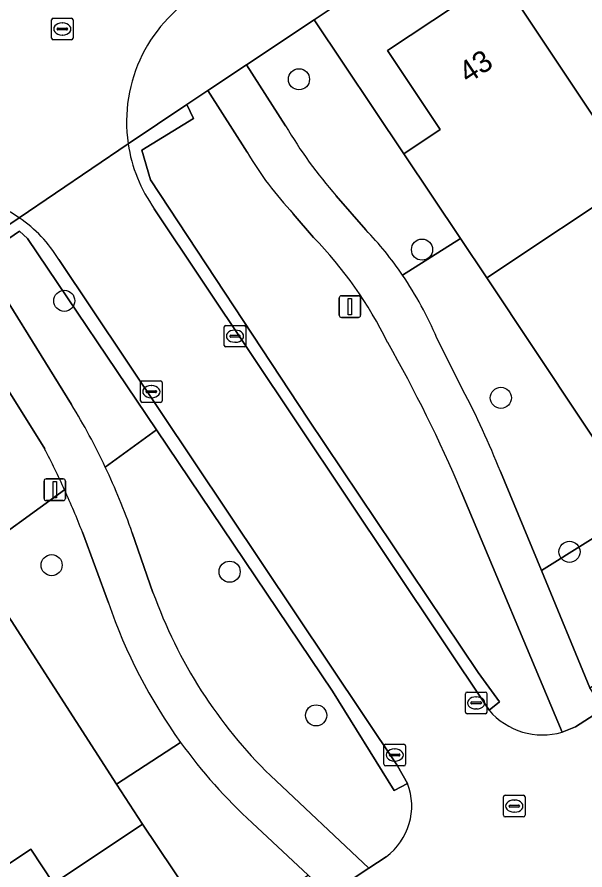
# Model space of a CAD drawing. Extents: x 158352 to 159489, y 383828 to 384603.
# Drawn here: x 158699.21 to 158725.52, y 384335.08 to 384374.6 of the extents above; entities that cross this region are included whole.
import ezdxf

# ---------------------------------------------------------------- set-up
doc = ezdxf.new("R2010")
doc.units = 0
for name, color, linetype in [('IMGEO_Boom', 7, 'Continuous'), ('IMGEO_Erf', 7, 'Continuous'), ('IMGEO_Groenvoorziening', 7, 'Continuous'), ('IMGEO_Haag', 7, 'Continuous'), ('IMGEO_Kolk', 7, 'Continuous'), ('IMGEO_Lichtmast', 7, 'Continuous'), ('IMGEO_Muur', 7, 'Continuous'), ('IMGEO_Pand', 7, 'Continuous'), ('IMGEO_Pand_nummerreeks', 7, 'Continuous'), ('IMGEO_Rijbaan_lokaal_open', 7, 'Continuous'), ('IMGEO_Rioolput', 7, 'Continuous'), ('IMGEO_Voetpad_gesloten', 7, 'Continuous'), ('IMGEO_Voetpad_open', 7, 'Continuous')]:
    doc.layers.add(name, color=color, linetype=linetype)

msp = doc.modelspace()

# ---------------------------------------------------------------- linework, layer by layer
at = {"layer": 'IMGEO_Boom'}
for centre in [(158712.272, 384371.717), (158717.972, 384363.823), (158701.4, 384361.451), (158721.624, 384356.956), (158724.801, 384349.824), (158700.816, 384349.204), (158709.059, 384348.902), (158713.066, 384342.244)]:
    msp.add_circle(centre, 0.489, dxfattribs=at)
at = {"layer": 'IMGEO_Erf'}
for points in [[(158753.174, 384401.294), (158712.97, 384374.475), (158717.126, 384368.26), (158718.813, 384369.388), (158716.368, 384373.045), (158721.573, 384376.51)], [(158727.843, 384367.089), (158720.967, 384362.517), (158727.592, 384352.549)], [(158684.114, 384325.544), (158687.812, 384328.006), (158688.865, 384326.424), (158689.665, 384326.961), (158688.612, 384328.543), (158692.312, 384331.006), (158693.365, 384329.425), (158694.658, 384330.292), (158693.602, 384331.872), (158696.723, 384333.957), (158699.844, 384336.043), (158700.9, 384334.463), (158702.178, 384335.311), (158705.018, 384337.202), (158703.821, 384339.058), (158697.064, 384349.538), (158689.651, 384344.598), (158684.664, 384341.256)]]:
    msp.add_lwpolyline(points, dxfattribs=at)
at = {"layer": 'IMGEO_Groenvoorziening'}
for points in [[(158712.97, 384374.475), (158709.84, 384372.387), (158711.653, 384369.562)], [(158717.07, 384362.641), (158719.749, 384364.339), (158717.126, 384368.26), (158712.97, 384374.475)], [(158709.873, 384368.34), (158708.044, 384371.19), (158707.074, 384370.542), (158707.385, 384369.905), (158704.999, 384368.433), (158705.402, 384367.055), (158712.693, 384355.962), (158720.569, 384344.237), (158721.565, 384342.867), (158721.08, 384342.484)], [(158712.693, 384355.962), (158705.402, 384367.055), (158704.999, 384368.433), (158707.385, 384369.905), (158707.074, 384370.542), (158704.359, 384368.731)], [(158714.002, 384366.316), (158715.365, 384364.748)], [(158705.57, 384365.721), (158721.08, 384342.484), (158721.565, 384342.867), (158720.569, 384344.237), (158712.693, 384355.962)], [(158699.316, 384365.295), (158697.75, 384364.255), (158698.031, 384363.799), (158699.322, 384364.675), (158699.704, 384364.332), (158705.665, 384355.479), (158713.823, 384343.363), (158716.687, 384338.771), (158717.302, 384339.096), (158716.829, 384339.908), (158701.145, 384363.368)], [(158712.94, 384364.388), (158712.009, 384365.488)], [(158699.704, 384364.332), (158699.322, 384364.675), (158698.031, 384363.799), (158697.75, 384364.255), (158697.233, 384363.912), (158701.74, 384356.644)], [(158703.3, 384353.75), (158705.665, 384355.479), (158699.704, 384364.332)], [(158720.967, 384362.517), (158719.749, 384364.339), (158717.07, 384362.641)], [(158700.493, 384354.599), (158695.416, 384362.705), (158690.486, 384359.432), (158694.612, 384353.216), (158697.064, 384349.538), (158701.417, 384352.687)], [(158721.602, 384353.545), (158723.502, 384348.951), (158727.919, 384351.717), (158727.575, 384352.237), (158727.446, 384352.432), (158727.592, 384352.549), (158720.967, 384362.517)], [(158718.661, 384359.724), (158719.851, 384357.347)], [(158705.665, 384355.479), (158703.3, 384353.75)], [(158717.302, 384339.096), (158716.687, 384338.771), (158713.823, 384343.363), (158705.665, 384355.479)], [(158701.417, 384352.687), (158697.064, 384349.538), (158703.821, 384339.058), (158706.791, 384340.99)], [(158724.469, 384341.47), (158719.789, 384352.617)], [(158703.45, 384347.456), (158702.242, 384350.73)], [(158704.548, 384350.708), (158705.51, 384347.945)], [(158706.791, 384340.99), (158703.821, 384339.058), (158705.018, 384337.202), (158708.555, 384331.94), (158710.956, 384333.528), (158710.879, 384333.644), (158712.697, 384334.843), (158710.101, 384337.266)], [(158710.948, 384339.452), (158715.512, 384335.167), (158716.309, 384335.695)]]:
    msp.add_lwpolyline(points, dxfattribs=at)
msp.add_lwpolyline([(158727.919, 384351.717), (158723.502, 384348.951), (158725.745, 384343.528), (158728.727, 384345.389), (158728.901, 384345.506), (158731.062, 384346.956)], close=True, dxfattribs=at)
for centre, radius, start, end in [((158729.547, 384380.038), 20.735, 210.3471, 221.4364), ((158711.218, 384369.742), 6.933, 188.3835, 215.4489), ((158723.329, 384376.192), 15.58, 210.265, 223.3976), ((158695.745, 384360.074), 6.326, 31.383, 55.6278), ((158703.198, 384353.159), 16.803, 34.354, 43.6061), ((158699.629, 384351.337), 18.641, 26.0267, 44.4344), ((158703.138, 384353.15), 16.857, 22.9533, 34.2649), ((158659, 384326.876), 66.015, 22.95031, 29.63378), ((158684.902, 384338.947), 39.497, 21.6908, 27.7658), ((158674.842, 384340.277), 31.487, 25.3341, 31.3194), ((158663.128, 384335.363), 42.025, 24.345, 27.2405), ((158674.921, 384340.33), 31.392, 19.3042, 25.3082), ((158663.788, 384335.672), 41.297, 21.3851, 24.332), ((158726.651, 384355.494), 22.448, 199.6503, 225.612), ((158726.772, 384355.41), 24.641, 198.8327, 215.8184), ((158723.552, 384344.574), 3.237, 220.2193, 286.466), ((158726.797, 384355.439), 24.678, 215.8379, 227.4254), ((158714.571, 384338.048), 2.925, 306.449, 20.9982)]:
    msp.add_arc(centre, radius, start, end, dxfattribs=at)
at = {"layer": 'IMGEO_Haag'}
for points in [[(158707.074, 384370.542), (158704.359, 384368.731)], [(158705.57, 384365.721), (158721.08, 384342.484), (158721.565, 384342.867), (158720.569, 384344.237), (158712.693, 384355.962), (158705.402, 384367.055), (158704.999, 384368.433), (158707.385, 384369.905), (158707.074, 384370.542)], [(158699.316, 384365.295), (158697.75, 384364.255), (158698.031, 384363.799), (158699.322, 384364.675), (158699.704, 384364.332), (158713.823, 384343.363), (158716.687, 384338.771), (158717.302, 384339.096), (158716.829, 384339.908), (158701.145, 384363.368)]]:
    msp.add_lwpolyline(points, dxfattribs=at)
for centre, radius, start, end in [((158711.218, 384369.742), 6.933, 188.3835, 215.4489), ((158695.745, 384360.074), 6.326, 31.383, 55.6278)]:
    msp.add_arc(centre, radius, start, end, dxfattribs=at)
at = {"layer": 'IMGEO_Kolk'}
for p, q in [((158708.808, 384359.387), (158708.808, 384360.239)), ((158708.883, 384360.313), (158709.735, 384360.313)), ((158709.809, 384360.239), (158709.809, 384359.387)), ((158709.067, 384359.807), (158709.067, 384359.819)), ((158709.505, 384359.77), (158709.107, 384359.77)), ((158709.11, 384359.856), (158709.508, 384359.856)), ((158709.296, 384360.093), (158709.321, 384360.093)), ((158709.551, 384359.819), (158709.551, 384359.807)), ((158709.319, 384359.533), (158709.294, 384359.533)), ((158709.735, 384359.313), (158708.883, 384359.313)), ((158704.933, 384356.817), (158704.933, 384357.669)), ((158705.008, 384357.743), (158705.86, 384357.743)), ((158705.421, 384357.523), (158705.446, 384357.523)), ((158705.934, 384357.669), (158705.934, 384356.817)), ((158705.192, 384357.237), (158705.192, 384357.249)), ((158705.63, 384357.2), (158705.232, 384357.2)), ((158705.235, 384357.286), (158705.633, 384357.286)), ((158705.444, 384356.963), (158705.419, 384356.963)), ((158705.676, 384357.249), (158705.676, 384357.237)), ((158705.86, 384356.743), (158705.008, 384356.743)), ((158719.98, 384342.397), (158719.98, 384343.249)), ((158720.055, 384343.323), (158720.907, 384343.323)), ((158720.981, 384343.249), (158720.981, 384342.397)), ((158720.239, 384342.817), (158720.239, 384342.829)), ((158720.677, 384342.78), (158720.279, 384342.78)), ((158720.282, 384342.866), (158720.68, 384342.866)), ((158720.468, 384343.103), (158720.493, 384343.103)), ((158720.723, 384342.829), (158720.723, 384342.817)), ((158720.491, 384342.543), (158720.466, 384342.543)), ((158720.907, 384342.323), (158720.055, 384342.323)), ((158716.207, 384339.982), (158716.207, 384340.834)), ((158716.282, 384340.908), (158717.134, 384340.908)), ((158717.208, 384340.834), (158717.208, 384339.982)), ((158716.466, 384340.402), (158716.466, 384340.414)), ((158716.509, 384340.451), (158716.907, 384340.451)), ((158716.695, 384340.688), (158716.72, 384340.688)), ((158716.95, 384340.414), (158716.95, 384340.402)), ((158716.904, 384340.365), (158716.506, 384340.365)), ((158716.718, 384340.128), (158716.693, 384340.128)), ((158717.134, 384339.908), (158716.282, 384339.908))]:
    msp.add_line(p, q, dxfattribs=at)
for points in [[(158708.808, 384359.387), (158708.808, 384360.239)], [(158708.883, 384360.313), (158709.735, 384360.313)], [(158709.809, 384360.239), (158709.809, 384359.387)], [(158709.735, 384359.313), (158708.883, 384359.313)], [(158704.933, 384356.817), (158704.933, 384357.669)], [(158705.008, 384357.743), (158705.86, 384357.743)], [(158705.934, 384357.669), (158705.934, 384356.817)], [(158705.86, 384356.743), (158705.008, 384356.743)], [(158719.98, 384342.397), (158719.98, 384343.249)], [(158720.055, 384343.323), (158720.907, 384343.323)], [(158720.981, 384343.249), (158720.981, 384342.397)], [(158720.907, 384342.323), (158720.055, 384342.323)], [(158716.207, 384339.982), (158716.207, 384340.834)], [(158716.282, 384340.908), (158717.134, 384340.908)], [(158717.208, 384340.834), (158717.208, 384339.982)], [(158717.134, 384339.908), (158716.282, 384339.908)]]:
    msp.add_lwpolyline(points, dxfattribs=at)
for centre, radius, start, end in [((158708.885, 384360.237), 0.0765, 91.552, 178.448), ((158708.885, 384360.237), 0.0765, 91.552, 178.448), ((158709.733, 384360.237), 0.0765, 1.552, 88.448), ((158709.733, 384360.237), 0.0765, 1.552, 88.448), ((158709.107, 384359.816), 0.0403, 85.8775, 175.7526), ((158709.104, 384359.806), 0.0366, 178.938, 274.7102), ((158709.508, 384359.813), 0.043, 264.8664, 352.4533), ((158709.512, 384359.818), 0.0386, 1.7309, 96.639), ((158708.885, 384359.389), 0.0765, 181.552, 268.448), ((158708.885, 384359.389), 0.0765, 181.552, 268.448), ((158709.733, 384359.389), 0.0765, 271.552, 358.448), ((158709.733, 384359.389), 0.0765, 271.552, 358.448), ((158705.01, 384357.667), 0.0765, 91.552, 178.448), ((158705.01, 384357.667), 0.0765, 91.552, 178.448), ((158705.858, 384357.667), 0.0765, 1.552, 88.448), ((158705.858, 384357.667), 0.0765, 1.552, 88.448), ((158705.232, 384357.246), 0.0403, 85.8775, 175.7526), ((158705.229, 384357.236), 0.0366, 178.938, 274.7102), ((158705.633, 384357.243), 0.043, 264.8664, 352.4533), ((158705.637, 384357.248), 0.0386, 1.7309, 96.639), ((158705.01, 384356.819), 0.0765, 181.552, 268.448), ((158705.01, 384356.819), 0.0765, 181.552, 268.448), ((158705.858, 384356.819), 0.0765, 271.552, 358.448), ((158705.858, 384356.819), 0.0765, 271.552, 358.448), ((158720.057, 384343.247), 0.0765, 91.552, 178.448), ((158720.057, 384343.247), 0.0765, 91.552, 178.448), ((158720.905, 384343.247), 0.0765, 1.552, 88.448), ((158720.905, 384343.247), 0.0765, 1.552, 88.448), ((158720.279, 384342.826), 0.0403, 85.8775, 175.7526), ((158720.276, 384342.816), 0.0366, 178.938, 274.7102), ((158720.68, 384342.823), 0.043, 264.8664, 352.4533), ((158720.684, 384342.828), 0.0386, 1.7309, 96.639), ((158720.057, 384342.399), 0.0765, 181.552, 268.448), ((158720.057, 384342.399), 0.0765, 181.552, 268.448), ((158720.905, 384342.399), 0.0765, 271.552, 358.448), ((158720.905, 384342.399), 0.0765, 271.552, 358.448), ((158716.284, 384340.832), 0.0765, 91.552, 178.448), ((158716.284, 384340.832), 0.0765, 91.552, 178.448), ((158717.132, 384340.832), 0.0765, 1.552, 88.448), ((158717.132, 384340.832), 0.0765, 1.552, 88.448), ((158716.506, 384340.411), 0.0403, 85.8775, 175.7526), ((158716.503, 384340.401), 0.0366, 178.938, 274.7102), ((158716.907, 384340.408), 0.043, 264.8664, 352.4533), ((158716.911, 384340.413), 0.0386, 1.7309, 96.639), ((158716.284, 384339.984), 0.0765, 181.552, 268.448), ((158716.284, 384339.984), 0.0765, 181.552, 268.448), ((158717.132, 384339.984), 0.0765, 271.552, 358.448), ((158717.132, 384339.984), 0.0765, 271.552, 358.448)]:
    msp.add_arc(centre, radius, start, end, dxfattribs=at)
for centre, major_axis, ratio, start_param, end_param in [((158709.295, 384359.813), (-0.387, 0.002), 0.722429, 4.712389, 7.853982), ((158709.32, 384359.813), (-0.39, 0.002), 0.717154, 1.570796, 4.712389), ((158705.42, 384357.243), (-0.387, 0.002), 0.722429, 4.712389, 7.853982), ((158705.445, 384357.243), (-0.39, 0.002), 0.717154, 1.570796, 4.712389), ((158720.467, 384342.823), (-0.387, 0.002), 0.722429, 4.712389, 7.853982), ((158720.492, 384342.823), (-0.39, 0.002), 0.717154, 1.570796, 4.712389), ((158716.694, 384340.408), (-0.387, 0.002), 0.722429, 4.712389, 7.853982), ((158716.719, 384340.408), (-0.39, 0.002), 0.717154, 1.570796, 4.712389)]:
    msp.add_ellipse(centre, major_axis=major_axis, ratio=ratio, start_param=start_param, end_param=end_param, dxfattribs=at)
at = {"layer": 'IMGEO_Lichtmast'}
for p, q in [((158714.135, 384360.783), (158714.135, 384361.583)), ((158714.135, 384361.583), (158714.135, 384360.783)), ((158714.235, 384361.683), (158715.025, 384361.683)), ((158715.025, 384361.683), (158714.235, 384361.683)), ((158715.125, 384361.583), (158715.125, 384360.783)), ((158715.125, 384360.783), (158715.125, 384361.583)), ((158715.025, 384360.683), (158714.235, 384360.683)), ((158714.235, 384360.683), (158715.025, 384360.683)), ((158700.463, 384352.299), (158700.463, 384353.099)), ((158700.463, 384353.099), (158700.463, 384352.299)), ((158700.563, 384353.199), (158701.353, 384353.199)), ((158701.353, 384353.199), (158700.563, 384353.199)), ((158701.453, 384353.099), (158701.453, 384352.299)), ((158701.453, 384352.299), (158701.453, 384353.099)), ((158701.353, 384352.199), (158700.563, 384352.199)), ((158700.563, 384352.199), (158701.353, 384352.199))]:
    msp.add_line(p, q, dxfattribs=at)
for points in [[(158714.555, 384361.558), (158714.705, 384361.558), (158714.705, 384360.808), (158714.555, 384360.808), (158714.555, 384361.558)], [(158700.883, 384353.074), (158701.033, 384353.074), (158701.033, 384352.324), (158700.883, 384352.324), (158700.883, 384353.074)]]:
    msp.add_lwpolyline(points, dxfattribs=at)
for centre, start, end in [((158714.235, 384361.583), 90, 180), ((158714.235, 384361.583), 90, 180), ((158715.025, 384361.583), 0, 90), ((158715.025, 384361.583), 360, 90), ((158714.235, 384360.783), 180, 270), ((158714.235, 384360.783), 180, 270), ((158715.025, 384360.783), 270, 0), ((158715.025, 384360.783), 270, 0), ((158700.563, 384353.099), 90, 180), ((158700.563, 384353.099), 90, 180), ((158701.353, 384353.099), 0, 90), ((158701.353, 384353.099), 360, 90), ((158700.563, 384352.299), 180, 270), ((158700.563, 384352.299), 180, 270), ((158701.353, 384352.299), 270, 0), ((158701.353, 384352.299), 270, 0)]:
    msp.add_arc(centre, 0.1, start, end, dxfattribs=at)
at = {"layer": 'IMGEO_Muur'}
for points in [[(158727.575, 384352.237), (158727.446, 384352.432), (158727.592, 384352.549), (158720.967, 384362.517)], [(158705.018, 384337.202), (158703.821, 384339.058), (158697.064, 384349.538)], [(158705.018, 384337.202), (158702.178, 384335.311)], [(158710.956, 384333.528), (158708.555, 384331.94), (158705.018, 384337.202)]]:
    msp.add_lwpolyline(points, dxfattribs=at)
at = {"layer": 'IMGEO_Pand'}
for points in [[(158731.6, 384372.593), (158726.714, 384379.933), (158721.573, 384376.51), (158727.843, 384367.089), (158732.988, 384370.513)], [(158721.573, 384376.51), (158716.368, 384373.045), (158718.813, 384369.388), (158717.126, 384368.26), (158719.749, 384364.339), (158720.967, 384362.517), (158727.843, 384367.089)], [(158696.723, 384333.957), (158697.779, 384332.378), (158700.9, 384334.463), (158699.844, 384336.043)]]:
    msp.add_lwpolyline(points, close=True, dxfattribs=at)
at = {"layer": 'IMGEO_Rijbaan_lokaal_open'}
for points in [[(158704.359, 384368.731), (158699.316, 384365.295)], [(158699.316, 384365.295), (158704.359, 384368.731)], [(158721.08, 384342.484), (158705.57, 384365.721)], [(158701.145, 384363.368), (158716.829, 384339.908), (158717.302, 384339.096)], [(158726.711, 384337.334), (158727.478, 384338.067), (158728.305, 384338.489), (158731.94, 384340.893), (158731.872, 384340.996), (158731.779, 384341.137), (158729.669, 384344.34), (158729.515, 384344.573), (158726.374, 384342.546), (158725.076, 384341.719), (158724.469, 384341.47)], [(158716.309, 384335.695), (158715.512, 384335.167), (158713.671, 384333.948), (158711.732, 384332.664), (158711.598, 384332.575), (158713.894, 384329.165), (158716.517, 384330.79), (158718.427, 384331.973), (158718.897, 384332.265)]]:
    msp.add_lwpolyline(points, dxfattribs=at)
for centre, radius, start, end in [((158711.228, 384369.747), 6.944, 118.6474, 188.416), ((158711.218, 384369.742), 6.933, 188.3835, 215.4489), ((158695.738, 384360.066), 6.336, 55.6168, 124.1744), ((158695.745, 384360.074), 6.326, 31.383, 55.6278), ((158723.552, 384344.574), 3.237, 220.2193, 286.466), ((158714.571, 384338.048), 2.925, 306.449, 20.9982)]:
    msp.add_arc(centre, radius, start, end, dxfattribs=at)
at = {"layer": 'IMGEO_Rioolput'}
for p, q in [((158700.81, 384373.619), (158700.81, 384374.471)), ((158700.885, 384374.545), (158701.737, 384374.545)), ((158701.811, 384374.471), (158701.811, 384373.619)), ((158701.069, 384374.039), (158701.069, 384374.051)), ((158701.507, 384374.002), (158701.109, 384374.002)), ((158701.112, 384374.088), (158701.51, 384374.088)), ((158701.298, 384374.325), (158701.323, 384374.325)), ((158701.553, 384374.051), (158701.553, 384374.039)), ((158701.321, 384373.765), (158701.296, 384373.765)), ((158701.737, 384373.545), (158700.885, 384373.545)), ((158721.745, 384337.615), (158721.745, 384338.467)), ((158721.82, 384338.541), (158722.672, 384338.541)), ((158722.746, 384338.467), (158722.746, 384337.615)), ((158722.004, 384338.035), (158722.004, 384338.047)), ((158722.442, 384337.998), (158722.044, 384337.998)), ((158722.047, 384338.084), (158722.445, 384338.084)), ((158722.233, 384338.321), (158722.258, 384338.321)), ((158722.488, 384338.047), (158722.488, 384338.035)), ((158722.256, 384337.761), (158722.231, 384337.761)), ((158722.672, 384337.541), (158721.82, 384337.541))]:
    msp.add_line(p, q, dxfattribs=at)
for points in [[(158700.81, 384373.619), (158700.81, 384374.471)], [(158700.885, 384374.545), (158701.737, 384374.545)], [(158701.811, 384374.471), (158701.811, 384373.619)], [(158701.737, 384373.545), (158700.885, 384373.545)], [(158721.745, 384337.615), (158721.745, 384338.467)], [(158721.82, 384338.541), (158722.672, 384338.541)], [(158722.746, 384338.467), (158722.746, 384337.615)], [(158722.672, 384337.541), (158721.82, 384337.541)]]:
    msp.add_lwpolyline(points, dxfattribs=at)
for centre, radius, start, end in [((158700.887, 384374.469), 0.0765, 91.552, 178.448), ((158700.887, 384374.469), 0.0765, 91.552, 178.448), ((158701.735, 384374.469), 0.0765, 1.552, 88.448), ((158701.735, 384374.469), 0.0765, 1.552, 88.448), ((158701.109, 384374.048), 0.0403, 85.8775, 175.7526), ((158701.106, 384374.038), 0.0366, 178.938, 274.7102), ((158701.51, 384374.045), 0.043, 264.8664, 352.4533), ((158701.514, 384374.05), 0.0386, 1.7309, 96.639), ((158700.887, 384373.621), 0.0765, 181.552, 268.448), ((158700.887, 384373.621), 0.0765, 181.552, 268.448), ((158701.735, 384373.621), 0.0765, 271.552, 358.448), ((158701.735, 384373.621), 0.0765, 271.552, 358.448), ((158721.822, 384338.465), 0.0765, 91.552, 178.448), ((158721.822, 384338.465), 0.0765, 91.552, 178.448), ((158722.67, 384338.465), 0.0765, 1.552, 88.448), ((158722.67, 384338.465), 0.0765, 1.552, 88.448), ((158722.044, 384338.044), 0.0403, 85.8775, 175.7526), ((158722.041, 384338.034), 0.0366, 178.938, 274.7102), ((158722.445, 384338.041), 0.043, 264.8664, 352.4533), ((158722.449, 384338.046), 0.0386, 1.7309, 96.639), ((158721.822, 384337.617), 0.0765, 181.552, 268.448), ((158721.822, 384337.617), 0.0765, 181.552, 268.448), ((158722.67, 384337.617), 0.0765, 271.552, 358.448), ((158722.67, 384337.617), 0.0765, 271.552, 358.448)]:
    msp.add_arc(centre, radius, start, end, dxfattribs=at)
for centre, major_axis, ratio, start_param, end_param in [((158701.297, 384374.045), (-0.387, 0.002), 0.722429, 4.712389, 7.853982), ((158701.322, 384374.045), (-0.39, 0.002), 0.717154, 1.570796, 4.712389), ((158722.232, 384338.041), (-0.387, 0.002), 0.722429, 4.712389, 7.853982), ((158722.257, 384338.041), (-0.39, 0.002), 0.717154, 1.570796, 4.712389)]:
    msp.add_ellipse(centre, major_axis=major_axis, ratio=ratio, start_param=start_param, end_param=end_param, dxfattribs=at)
at = {"layer": 'IMGEO_Voetpad_gesloten'}
for points in [[(158711.653, 384369.562), (158709.84, 384372.387), (158708.044, 384371.19), (158709.873, 384368.34)], [(158715.365, 384364.748), (158714.002, 384366.316)], [(158712.009, 384365.488), (158712.94, 384364.388)], [(158701.74, 384356.644), (158697.233, 384363.912), (158695.416, 384362.705), (158700.493, 384354.599)], [(158719.851, 384357.347), (158718.661, 384359.724)], [(158719.789, 384352.617), (158724.469, 384341.47), (158725.076, 384341.719), (158726.374, 384342.546), (158725.745, 384343.528), (158723.502, 384348.951), (158721.602, 384353.545)], [(158702.242, 384350.73), (158703.45, 384347.456)], [(158705.51, 384347.945), (158704.548, 384350.708)], [(158710.101, 384337.266), (158712.697, 384334.843), (158713.671, 384333.948), (158715.512, 384335.167), (158710.948, 384339.452)]]:
    msp.add_lwpolyline(points, dxfattribs=at)
for centre, radius, start, end in [((158729.547, 384380.038), 20.735, 210.3471, 221.4364), ((158723.329, 384376.192), 15.58, 210.265, 223.3976), ((158703.198, 384353.159), 16.803, 34.354, 43.6061), ((158699.629, 384351.337), 18.641, 26.0267, 44.4344), ((158703.138, 384353.15), 16.857, 22.9533, 34.2649), ((158659, 384326.876), 66.015, 22.95031, 29.63378), ((158684.902, 384338.947), 39.497, 21.6908, 27.7658), ((158674.842, 384340.277), 31.487, 25.3341, 31.3194), ((158663.128, 384335.363), 42.025, 24.345, 27.2405), ((158674.921, 384340.33), 31.392, 19.3042, 25.3082), ((158663.788, 384335.672), 41.297, 21.3851, 24.332), ((158726.651, 384355.494), 22.448, 199.6503, 225.612), ((158726.772, 384355.41), 24.641, 198.8327, 215.8184), ((158726.797, 384355.439), 24.678, 215.8379, 227.4254)]:
    msp.add_arc(centre, radius, start, end, dxfattribs=at)
at = {"layer": 'IMGEO_Voetpad_open'}
for points in [[(158704.359, 384368.731), (158707.074, 384370.542), (158708.044, 384371.19), (158709.84, 384372.387), (158712.97, 384374.475), (158753.174, 384401.294), (158753.504, 384404.062)], [(158686.972, 384357.1), (158690.486, 384359.432), (158695.416, 384362.705), (158697.233, 384363.912), (158697.75, 384364.255), (158699.316, 384365.295)], [(158708.25, 384330.387), (158711.527, 384332.68), (158710.956, 384333.528), (158708.555, 384331.94), (158705.018, 384337.202), (158702.178, 384335.311), (158700.9, 384334.463), (158697.779, 384332.378), (158694.658, 384330.292), (158693.365, 384329.425), (158689.665, 384326.961), (158688.865, 384326.424), (158685.166, 384323.963)]]:
    msp.add_lwpolyline(points, dxfattribs=at)
for centre, radius, start, end in [((158711.228, 384369.747), 6.944, 118.6474, 188.416), ((158695.738, 384360.066), 6.336, 55.6168, 124.1744)]:
    msp.add_arc(centre, radius, start, end, dxfattribs=at)

# ---------------------------------------------------------------- texts
at = {"layer": 'IMGEO_Pand_nummerreeks'}
msp.add_text('43', height=1, rotation=33.6498, dxfattribs=at).set_placement((158720.103, 384371.494))

doc.saveas('drawing.dxf')
